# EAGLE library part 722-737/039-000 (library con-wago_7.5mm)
Serie 722, Federleiste mit Verriegelungsklinken / Series 722, Female connector with locking levers Polzahl / Pole No.: 7 Bemessungsspannung / Rated Voltage: 400 V Nennstrom / Nominal Current: 12 A Farbe / Color: xxxx / xxxx Stand: 01.01.2012. Die jeweils aktuellen Daten zu diesem Artikel finden Sie in unserem Produktkatalog, den Sie unter www.wago.com einsehen können. As of: 01/01/2012. Please find the newest data for this article in our product catalogue, which can be viewed under www.wago.com.
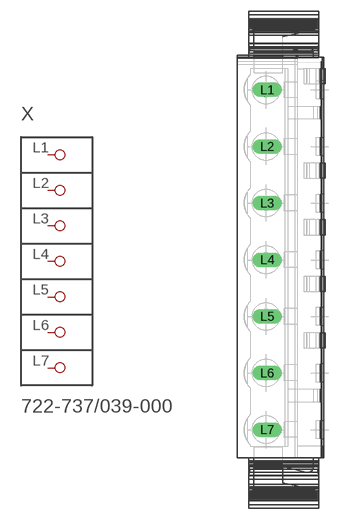
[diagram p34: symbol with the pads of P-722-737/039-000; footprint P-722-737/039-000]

Designator prefix X

## 722-737/039-000  [P-722-737/039-000]
L1  P1
L2  P2
L3  P3
L4  P4
L5  P5
L6  P6
L7  P7

## Footprint P-722-737/039-000 (pad centres in mm)
drill 1.3 long: L1 -2.085,22.5; L2 -2.085,15; L3 -2.085,7.5; L4 -2.085,0; L5 -2.085,-7.5; L6 -2.085,-15; L7 -2.085,-22.5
